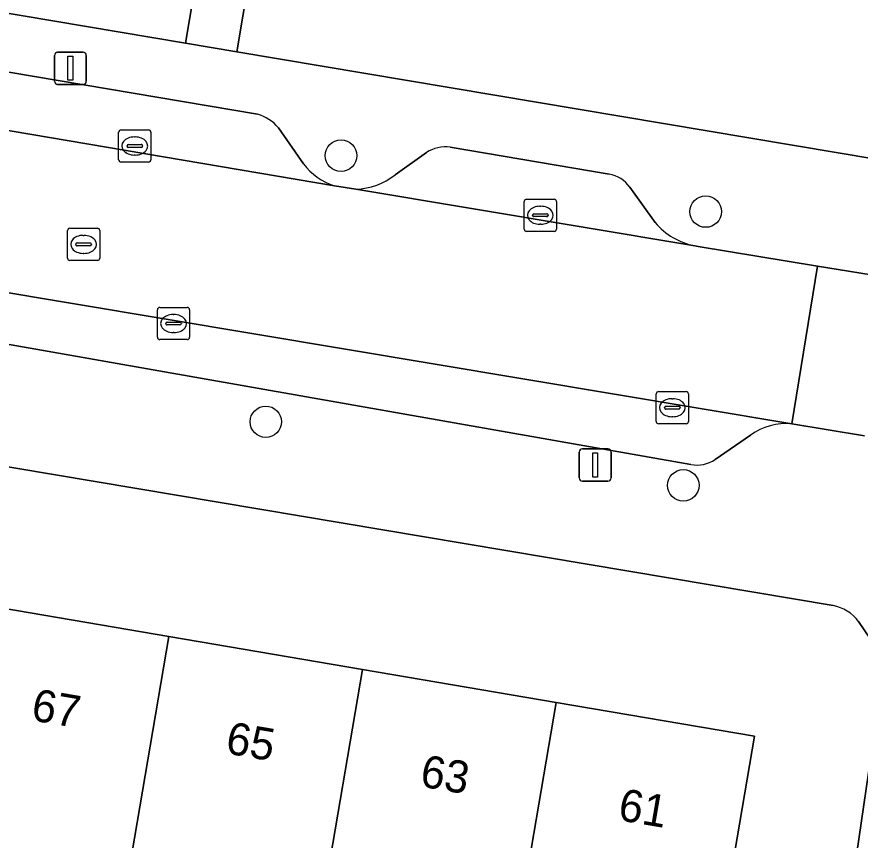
# Model space of a CAD drawing. Extents: x 163683 to 164494, y 382709 to 383872.
# Drawn here: x 163770.7 to 163796.88, y 383135.79 to 383161.35 of the extents above; entities that cross this region are included whole.
import ezdxf

# ---------------------------------------------------------------- set-up
doc = ezdxf.new("R2010")
doc.units = 0
for name, color, linetype in [('IMGEO_Boom', 7, 'Continuous'), ('IMGEO_Erf', 7, 'Continuous'), ('IMGEO_Kolk', 7, 'Continuous'), ('IMGEO_Lichtmast', 7, 'Continuous'), ('IMGEO_Pand', 7, 'Continuous'), ('IMGEO_Pand_nummerreeks', 7, 'Continuous'), ('IMGEO_Parkeervlak_open', 7, 'Continuous'), ('IMGEO_Rijbaan_lokaal_open', 7, 'Continuous'), ('IMGEO_Rioolput', 7, 'Continuous'), ('IMGEO_Voetpad_open', 7, 'Continuous')]:
    doc.layers.add(name, color=color, linetype=linetype)

msp = doc.modelspace()

# ---------------------------------------------------------------- linework, layer by layer
at = {"layer": 'IMGEO_Boom'}
for centre in [(163780.76, 383157.041), (163792.081, 383155.305), (163778.425, 383148.778), (163791.387, 383146.804)]:
    msp.add_circle(centre, 0.489, dxfattribs=at)
at = {"layer": 'IMGEO_Erf'}
for points in [[(163752.432, 383164.492), (163775.936, 383160.536), (163776.937, 383166.483), (163774.156, 383166.948), (163774.821, 383170.925), (163777.602, 383170.46), (163778.046, 383173.311), (163775.277, 383173.742), (163775.919, 383177.869), (163776.362, 383180.707), (163779.437, 383180.228), (163780.286, 383184.818)], [(163797.751, 383163.599), (163792.889, 383164.412), (163788.294, 383165.181), (163783.536, 383165.977), (163778.626, 383166.798), (163777.527, 383160.268), (163798.786, 383156.69)], [(163796.038, 383143.072), (163751.496, 383150.561), (163750.514, 383150.658)], [(163748.411, 383148.954), (163744.898, 383125.783), (163747.926, 383125.324), (163748.934, 383132.13), (163753.881, 383131.397), (163754.891, 383131.248), (163754.319, 383127.255), (163757.947, 383126.718), (163757.472, 383123.911), (163769.436, 383121.886), (163769.505, 383122.297), (163774.597, 383121.466), (163775.052, 383124.253), (163778.468, 383123.695), (163782.244, 383123.079), (163781.789, 383120.292), (163784.189, 383119.855), (163784.237, 383120.178), (163784.607, 383122.688), (163790.76, 383121.781), (163790.342, 383118.948), (163794.3, 383118.433), (163794.798, 383121.842), (163797.575, 383140.863)], [(163797.395, 383141.744), (163796.829, 383142.581)]]:
    msp.add_lwpolyline(points, dxfattribs=at)
msp.add_lwpolyline([(163749.991, 383138.997), (163751.219, 383146.224), (163757.382, 383145.176), (163763.393, 383144.155), (163769.405, 383143.133), (163775.416, 383142.111), (163781.428, 383141.089), (163787.44, 383140.067), (163793.599, 383139.02), (163792.37, 383131.793), (163786.21, 383132.84), (163780.198, 383133.862), (163774.186, 383134.884), (163768.175, 383135.906), (163762.162, 383136.928), (163756.151, 383137.95)], close=True, dxfattribs=at)
msp.add_arc((163795.795, 383141.798), 1.297, 37.1307, 79.2108, dxfattribs=at)
at = {"layer": 'IMGEO_Kolk'}
for p, q in [((163773.856, 383156.915), (163773.856, 383157.767)), ((163773.931, 383157.841), (163774.783, 383157.841)), ((163774.857, 383157.767), (163774.857, 383156.915)), ((163774.344, 383157.621), (163774.369, 383157.621)), ((163774.115, 383157.335), (163774.115, 383157.347)), ((163774.553, 383157.298), (163774.155, 383157.298)), ((163774.158, 383157.384), (163774.556, 383157.384)), ((163774.599, 383157.347), (163774.599, 383157.335)), ((163774.367, 383157.061), (163774.342, 383157.061)), ((163774.783, 383156.841), (163773.931, 383156.841)), ((163786.524, 383155.69), (163787.376, 383155.69)), ((163786.449, 383154.764), (163786.449, 383155.616)), ((163786.937, 383155.47), (163786.962, 383155.47)), ((163787.45, 383155.616), (163787.45, 383154.764)), ((163786.708, 383155.184), (163786.708, 383155.196)), ((163787.146, 383155.147), (163786.748, 383155.147)), ((163786.751, 383155.233), (163787.149, 383155.233)), ((163787.192, 383155.196), (163787.192, 383155.184)), ((163786.96, 383154.91), (163786.935, 383154.91)), ((163787.376, 383154.69), (163786.524, 383154.69)), ((163775.059, 383151.403), (163775.059, 383152.255)), ((163775.134, 383152.329), (163775.986, 383152.329)), ((163776.06, 383152.255), (163776.06, 383151.403)), ((163775.547, 383152.109), (163775.572, 383152.109)), ((163775.318, 383151.823), (163775.318, 383151.835)), ((163775.756, 383151.786), (163775.358, 383151.786)), ((163775.361, 383151.872), (163775.759, 383151.872)), ((163775.802, 383151.835), (163775.802, 383151.823)), ((163775.57, 383151.549), (163775.545, 383151.549)), ((163775.986, 383151.329), (163775.134, 383151.329)), ((163790.548, 383148.79), (163790.548, 383149.642)), ((163790.623, 383149.716), (163791.475, 383149.716)), ((163791.549, 383149.642), (163791.549, 383148.79)), ((163791.036, 383149.496), (163791.061, 383149.496)), ((163790.807, 383149.21), (163790.807, 383149.222)), ((163791.245, 383149.173), (163790.847, 383149.173)), ((163790.85, 383149.259), (163791.248, 383149.259)), ((163791.291, 383149.222), (163791.291, 383149.21)), ((163791.059, 383148.936), (163791.034, 383148.936)), ((163791.475, 383148.716), (163790.623, 383148.716))]:
    msp.add_line(p, q, dxfattribs=at)
for points in [[(163773.856, 383156.915), (163773.856, 383157.767)], [(163773.931, 383157.841), (163774.783, 383157.841)], [(163774.857, 383157.767), (163774.857, 383156.915)], [(163774.783, 383156.841), (163773.931, 383156.841)], [(163786.524, 383155.69), (163787.376, 383155.69)], [(163786.449, 383154.764), (163786.449, 383155.616)], [(163787.45, 383155.616), (163787.45, 383154.764)], [(163787.376, 383154.69), (163786.524, 383154.69)], [(163775.059, 383151.403), (163775.059, 383152.255)], [(163775.134, 383152.329), (163775.986, 383152.329)], [(163776.06, 383152.255), (163776.06, 383151.403)], [(163775.986, 383151.329), (163775.134, 383151.329)], [(163790.548, 383148.79), (163790.548, 383149.642)], [(163790.623, 383149.716), (163791.475, 383149.716)], [(163791.549, 383149.642), (163791.549, 383148.79)], [(163791.475, 383148.716), (163790.623, 383148.716)]]:
    msp.add_lwpolyline(points, dxfattribs=at)
for centre, radius, start, end in [((163773.933, 383157.765), 0.0765, 91.552, 178.448), ((163773.933, 383157.765), 0.0765, 91.552, 178.448), ((163774.781, 383157.765), 0.0765, 1.552, 88.448), ((163774.781, 383157.765), 0.0765, 1.552, 88.448), ((163774.155, 383157.344), 0.0403, 85.8775, 175.7526), ((163774.152, 383157.334), 0.0366, 178.938, 274.7102), ((163774.556, 383157.341), 0.043, 264.8664, 352.4533), ((163774.56, 383157.346), 0.0386, 1.7309, 96.639), ((163773.933, 383156.917), 0.0765, 181.552, 268.448), ((163773.933, 383156.917), 0.0765, 181.552, 268.448), ((163774.781, 383156.917), 0.0765, 271.552, 358.448), ((163774.781, 383156.917), 0.0765, 271.552, 358.448), ((163786.526, 383155.614), 0.0765, 91.552, 178.448), ((163786.526, 383155.614), 0.0765, 91.552, 178.448), ((163787.374, 383155.614), 0.0765, 1.552, 88.448), ((163787.374, 383155.614), 0.0765, 1.552, 88.448), ((163786.748, 383155.193), 0.0403, 85.8775, 175.7526), ((163786.745, 383155.183), 0.0366, 178.938, 274.7102), ((163787.149, 383155.19), 0.043, 264.8664, 352.4533), ((163787.153, 383155.195), 0.0386, 1.7309, 96.639), ((163786.526, 383154.766), 0.0765, 181.552, 268.448), ((163786.526, 383154.766), 0.0765, 181.552, 268.448), ((163787.374, 383154.766), 0.0765, 271.552, 358.448), ((163787.374, 383154.766), 0.0765, 271.552, 358.448), ((163775.136, 383152.253), 0.0765, 91.552, 178.448), ((163775.136, 383152.253), 0.0765, 91.552, 178.448), ((163775.984, 383152.253), 0.0765, 1.552, 88.448), ((163775.984, 383152.253), 0.0765, 1.552, 88.448), ((163775.358, 383151.832), 0.0403, 85.8775, 175.7526), ((163775.355, 383151.822), 0.0366, 178.938, 274.7102), ((163775.759, 383151.829), 0.043, 264.8664, 352.4533), ((163775.763, 383151.834), 0.0386, 1.7309, 96.639), ((163775.136, 383151.405), 0.0765, 181.552, 268.448), ((163775.136, 383151.405), 0.0765, 181.552, 268.448), ((163775.984, 383151.405), 0.0765, 271.552, 358.448), ((163775.984, 383151.405), 0.0765, 271.552, 358.448), ((163790.625, 383149.64), 0.0765, 91.552, 178.448), ((163790.625, 383149.64), 0.0765, 91.552, 178.448), ((163791.473, 383149.64), 0.0765, 1.552, 88.448), ((163791.473, 383149.64), 0.0765, 1.552, 88.448), ((163790.847, 383149.219), 0.0403, 85.8775, 175.7526), ((163790.844, 383149.209), 0.0366, 178.938, 274.7102), ((163791.248, 383149.216), 0.043, 264.8664, 352.4533), ((163791.252, 383149.221), 0.0386, 1.7309, 96.639), ((163790.625, 383148.792), 0.0765, 181.552, 268.448), ((163790.625, 383148.792), 0.0765, 181.552, 268.448), ((163791.473, 383148.792), 0.0765, 271.552, 358.448), ((163791.473, 383148.792), 0.0765, 271.552, 358.448)]:
    msp.add_arc(centre, radius, start, end, dxfattribs=at)
for centre, major_axis, ratio, start_param, end_param in [((163774.343, 383157.341), (-0.387, 0.002), 0.722429, 4.712389, 7.853982), ((163774.368, 383157.341), (-0.39, 0.002), 0.717154, 1.570796, 4.712389), ((163786.936, 383155.19), (-0.387, 0.002), 0.722429, 4.712389, 7.853982), ((163786.961, 383155.19), (-0.39, 0.002), 0.717154, 1.570796, 4.712389), ((163775.546, 383151.829), (-0.387, 0.002), 0.722429, 4.712389, 7.853982), ((163775.571, 383151.829), (-0.39, 0.002), 0.717154, 1.570796, 4.712389), ((163791.035, 383149.216), (-0.387, 0.002), 0.722429, 4.712389, 7.853982), ((163791.06, 383149.216), (-0.39, 0.002), 0.717154, 1.570796, 4.712389)]:
    msp.add_ellipse(centre, major_axis=major_axis, ratio=ratio, start_param=start_param, end_param=end_param, dxfattribs=at)
at = {"layer": 'IMGEO_Lichtmast'}
for p, q in [((163771.861, 383159.355), (163771.861, 383160.155)), ((163771.861, 383160.155), (163771.861, 383159.355)), ((163771.961, 383160.255), (163772.751, 383160.255)), ((163772.751, 383160.255), (163771.961, 383160.255)), ((163772.851, 383160.155), (163772.851, 383159.355)), ((163772.851, 383159.355), (163772.851, 383160.155)), ((163772.751, 383159.255), (163771.961, 383159.255)), ((163771.961, 383159.255), (163772.751, 383159.255)), ((163788.155, 383147.039), (163788.155, 383147.839)), ((163788.155, 383147.839), (163788.155, 383147.039)), ((163788.255, 383147.939), (163789.045, 383147.939)), ((163789.045, 383147.939), (163788.255, 383147.939)), ((163789.145, 383147.839), (163789.145, 383147.039)), ((163789.145, 383147.039), (163789.145, 383147.839)), ((163789.045, 383146.939), (163788.255, 383146.939)), ((163788.255, 383146.939), (163789.045, 383146.939))]:
    msp.add_line(p, q, dxfattribs=at)
for points in [[(163772.281, 383160.13), (163772.431, 383160.13), (163772.431, 383159.38), (163772.281, 383159.38), (163772.281, 383160.13)], [(163788.575, 383147.814), (163788.725, 383147.814), (163788.725, 383147.064), (163788.575, 383147.064), (163788.575, 383147.814)]]:
    msp.add_lwpolyline(points, dxfattribs=at)
for centre, start, end in [((163771.961, 383160.155), 90, 180), ((163771.961, 383160.155), 90, 180), ((163772.751, 383160.155), 0, 90), ((163772.751, 383160.155), 360, 90), ((163771.961, 383159.355), 180, 270), ((163771.961, 383159.355), 180, 270), ((163772.751, 383159.355), 270, 0), ((163772.751, 383159.355), 270, 0), ((163788.255, 383147.839), 90, 180), ((163788.255, 383147.839), 90, 180), ((163789.045, 383147.839), 0, 90), ((163789.045, 383147.839), 360, 90), ((163788.255, 383147.039), 180, 270), ((163788.255, 383147.039), 180, 270), ((163789.045, 383147.039), 270, 0), ((163789.045, 383147.039), 270, 0)]:
    msp.add_arc(centre, 0.1, start, end, dxfattribs=at)
at = {"layer": 'IMGEO_Pand'}
for points in [[(163769.405, 383143.133), (163768.175, 383135.906), (163774.186, 383134.884), (163775.416, 383142.111)], [(163781.428, 383141.089), (163775.416, 383142.111), (163774.186, 383134.884), (163780.198, 383133.862)], [(163781.428, 383141.089), (163780.198, 383133.862), (163786.21, 383132.84), (163787.44, 383140.067)], [(163786.21, 383132.84), (163792.37, 383131.793), (163793.599, 383139.02), (163787.44, 383140.067)]]:
    msp.add_lwpolyline(points, close=True, dxfattribs=at)
at = {"layer": 'IMGEO_Parkeervlak_open'}
for points in [[(163778.162, 383158.325), (163760.387, 383161.334)], [(163757.539, 383160.01), (163780.555, 383156.103)], [(163779.595, 383156.787), (163778.818, 383157.905)], [(163789.087, 383156.463), (163784.151, 383157.307)], [(163783.411, 383157.139), (163782.437, 383156.45)], [(163781.223, 383156.003), (163791.741, 383154.239)], [(163790.514, 383154.963), (163789.723, 383156.058)], [(163794.759, 383148.72), (163752.985, 383155.705)], [(163755.107, 383153.876), (163791.623, 383147.449)], [(163792.377, 383147.605), (163793.472, 383148.365)]]:
    msp.add_lwpolyline(points, dxfattribs=at)
for centre, radius, start, end in [((163777.833, 383157.089), 1.279, 39.641, 75.1007), ((163784.029, 383156.132), 1.181, 84.0573, 121.5244), ((163781.173, 383157.987), 1.983, 217.2366, 251.8237), ((163781.18, 383157.993), 1.99, 271.2502, 309.1776), ((163788.958, 383155.559), 0.914, 33.1395, 81.8831), ((163792.177, 383156.379), 2.184, 220.418, 258.496), ((163794.617, 383146.724), 2.001, 85.9326, 124.9089), ((163791.798, 383148.506), 1.071, 260.6218, 302.7569)]:
    msp.add_arc(centre, radius, start, end, dxfattribs=at)
at = {"layer": 'IMGEO_Rijbaan_lokaal_open'}
msp.add_lwpolyline([(163752.757, 383160.82), (163751.888, 383155.93), (163752.985, 383155.705), (163794.759, 383148.72), (163795.558, 383153.614), (163791.85, 383154.22), (163791.741, 383154.239), (163781.223, 383156.003), (163780.555, 383156.103), (163757.539, 383160.01)], close=True, dxfattribs=at)
msp.add_lwpolyline([(163797.86, 383153.238), (163795.558, 383153.614), (163794.759, 383148.72), (163797.015, 383148.345)], dxfattribs=at)
at = {"layer": 'IMGEO_Rioolput'}
for p, q in [((163772.267, 383153.861), (163772.267, 383154.713)), ((163772.342, 383154.787), (163773.194, 383154.787)), ((163773.268, 383154.713), (163773.268, 383153.861)), ((163772.569, 383154.33), (163772.967, 383154.33)), ((163772.755, 383154.567), (163772.78, 383154.567)), ((163772.526, 383154.281), (163772.526, 383154.293)), ((163772.964, 383154.244), (163772.566, 383154.244)), ((163773.01, 383154.293), (163773.01, 383154.281)), ((163772.778, 383154.007), (163772.753, 383154.007)), ((163773.194, 383153.787), (163772.342, 383153.787))]:
    msp.add_line(p, q, dxfattribs=at)
for points in [[(163772.267, 383153.861), (163772.267, 383154.713)], [(163772.342, 383154.787), (163773.194, 383154.787)], [(163773.268, 383154.713), (163773.268, 383153.861)], [(163773.194, 383153.787), (163772.342, 383153.787)]]:
    msp.add_lwpolyline(points, dxfattribs=at)
for centre, radius, start, end in [((163772.344, 383154.711), 0.0765, 91.552, 178.448), ((163772.344, 383154.711), 0.0765, 91.552, 178.448), ((163773.192, 383154.711), 0.0765, 1.552, 88.448), ((163773.192, 383154.711), 0.0765, 1.552, 88.448), ((163772.566, 383154.29), 0.0403, 85.8775, 175.7526), ((163772.971, 383154.292), 0.0386, 1.7309, 96.639), ((163772.563, 383154.28), 0.0366, 178.938, 274.7102), ((163772.967, 383154.287), 0.043, 264.8664, 352.4533), ((163772.344, 383153.863), 0.0765, 181.552, 268.448), ((163772.344, 383153.863), 0.0765, 181.552, 268.448), ((163773.192, 383153.863), 0.0765, 271.552, 358.448), ((163773.192, 383153.863), 0.0765, 271.552, 358.448)]:
    msp.add_arc(centre, radius, start, end, dxfattribs=at)
for centre, major_axis, ratio, start_param, end_param in [((163772.754, 383154.287), (-0.387, 0.002), 0.722429, 4.712389, 7.853982), ((163772.779, 383154.287), (-0.39, 0.002), 0.717154, 1.570796, 4.712389)]:
    msp.add_ellipse(centre, major_axis=major_axis, ratio=ratio, start_param=start_param, end_param=end_param, dxfattribs=at)
at = {"layer": 'IMGEO_Voetpad_open'}
msp.add_lwpolyline([(163782.072, 383185.979), (163780.526, 383186.36), (163780.286, 383184.818), (163779.437, 383180.228), (163778.989, 383177.352), (163778.352, 383173.263), (163778.046, 383173.311), (163777.602, 383170.46), (163776.937, 383166.483), (163775.936, 383160.536), (163777.527, 383160.268), (163778.626, 383166.798), (163779.452, 383171.73), (163779.96, 383174.767)], close=True, dxfattribs=at)
for points in [[(163798.786, 383156.69), (163777.527, 383160.268), (163775.936, 383160.536), (163752.432, 383164.492)], [(163760.387, 383161.334), (163778.162, 383158.325)], [(163778.818, 383157.905), (163779.595, 383156.787)], [(163784.151, 383157.307), (163789.087, 383156.463)], [(163782.437, 383156.45), (163783.411, 383157.139)], [(163780.555, 383156.103), (163781.223, 383156.003)], [(163789.723, 383156.058), (163790.514, 383154.963)], [(163791.741, 383154.239), (163791.85, 383154.22), (163795.558, 383153.614), (163797.86, 383153.238)], [(163791.623, 383147.449), (163755.107, 383153.876)], [(163750.514, 383150.658), (163751.496, 383150.561), (163796.038, 383143.072)], [(163797.015, 383148.345), (163794.759, 383148.72)], [(163793.472, 383148.365), (163792.377, 383147.605)], [(163796.829, 383142.581), (163797.395, 383141.744), (163801.766, 383141.219)], [(163797.575, 383140.863), (163794.798, 383121.842), (163794.3, 383118.433), (163794.072, 383116.877), (163787.38, 383071.224), (163786.899, 383067.944), (163777.727, 383005.372), (163777.694, 383005.149), (163776.949, 383005.218), (163776.758, 383003.963), (163772.686, 382977.166), (163771.846, 382971.711), (163778.507, 382970.637), (163778.631, 382971.224)]]:
    msp.add_lwpolyline(points, dxfattribs=at)
for centre, radius, start, end in [((163777.833, 383157.089), 1.279, 39.641, 75.1007), ((163784.029, 383156.132), 1.181, 84.0573, 121.5244), ((163781.173, 383157.987), 1.983, 217.2366, 251.8237), ((163781.18, 383157.993), 1.99, 271.2502, 309.1776), ((163788.958, 383155.559), 0.914, 33.1395, 81.8831), ((163792.177, 383156.379), 2.184, 220.418, 258.496), ((163794.617, 383146.724), 2.001, 85.9326, 124.9089), ((163791.798, 383148.506), 1.071, 260.6218, 302.7569), ((163795.795, 383141.798), 1.297, 37.1307, 79.2108)]:
    msp.add_arc(centre, radius, start, end, dxfattribs=at)

# ---------------------------------------------------------------- texts
at = {"layer": 'IMGEO_Pand_nummerreeks'}
for s, p in [('67', (163771.107, 383139.516)), ('65', (163777.143, 383138.49)), ('63', (163783.18, 383137.464)), ('61', (163789.328, 383136.419))]:
    msp.add_text(s, height=1, rotation=350.3527, dxfattribs=at).set_placement(p)

doc.saveas('drawing.dxf')
